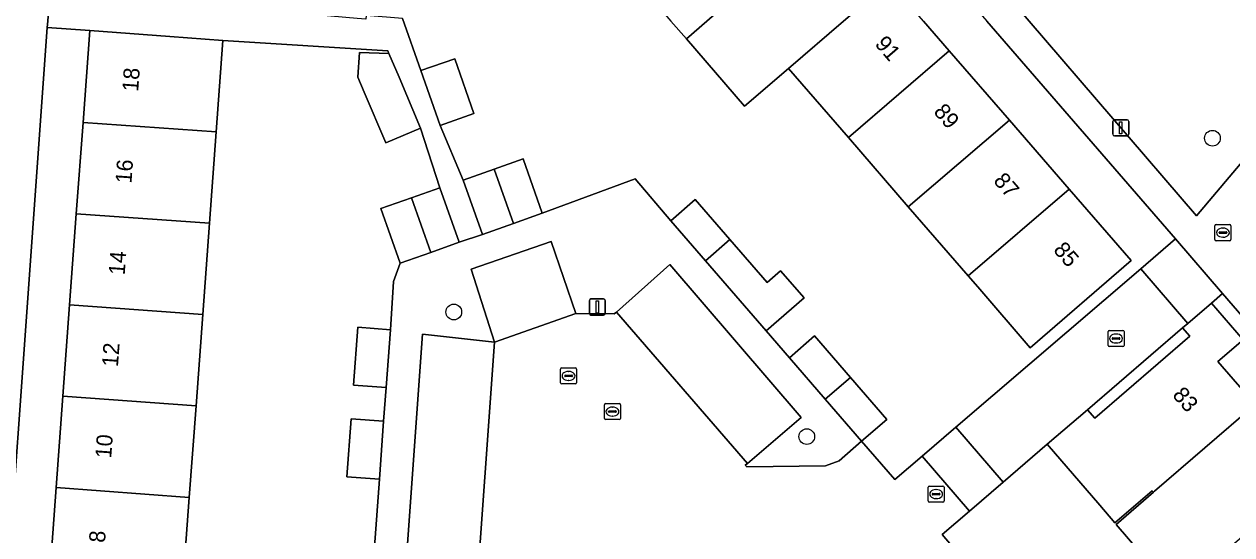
# Model space of a CAD drawing. Extents: x 160304 to 160955, y 383684 to 384161.
# Drawn here: x 160524.6 to 160599.7, y 383968 to 383999.8 of the extents above; entities that cross this region are included whole.
import ezdxf

# ---------------------------------------------------------------- set-up
doc = ezdxf.new("R2010")
doc.units = 0
for name, color, linetype in [('IMGEO_Boom', 7, 'Continuous'), ('IMGEO_Erf', 7, 'Continuous'), ('IMGEO_Groenvoorziening', 7, 'Continuous'), ('IMGEO_Kolk', 7, 'Continuous'), ('IMGEO_Lichtmast', 7, 'Continuous'), ('IMGEO_Muur', 7, 'Continuous'), ('IMGEO_Pand', 7, 'Continuous'), ('IMGEO_Pand_nummerreeks', 7, 'Continuous'), ('IMGEO_Parkeervlak_open', 7, 'Continuous'), ('IMGEO_Rijbaan_lokaal_open', 7, 'Continuous'), ('IMGEO_Rioolput', 7, 'Continuous'), ('IMGEO_Voetpad_open', 7, 'Continuous')]:
    doc.layers.add(name, color=color, linetype=linetype)

msp = doc.modelspace()

# ---------------------------------------------------------------- linework, layer by layer
at = {"layer": 'IMGEO_Boom'}
for centre in [(160598.466, 383992.708), (160551.283, 383981.891), (160573.236, 383974.138)]:
    msp.add_circle(centre, 0.489, dxfattribs=at)
at = {"layer": 'IMGEO_Erf'}
for points in [[(160527.389, 383982.34), (160527.806, 383988.006), (160528.225, 383993.695), (160528.645, 383999.401), (160525.998, 383999.592), (160522.302, 383948.238), (160524.866, 383948.053), (160525.298, 383953.917), (160525.715, 383959.593), (160526.134, 383965.285), (160526.553, 383970.972), (160526.971, 383976.651)], [(160599.096, 383983.036), (160598.414, 383982.45), (160600.377, 383980.168), (160598.806, 383978.817), (160601.124, 383976.14), (160604.854, 383971.83), (160608.58, 383967.526), (160612.311, 383963.216), (160616.036, 383958.913), (160619.776, 383954.593), (160623.509, 383950.28), (160627.234, 383945.977), (160630.965, 383941.666), (160634.791, 383937.247), (160631.011, 383933.975), (160628.454, 383931.789), (160638.073, 383937.196), (160637.034, 383939.15)], [(160590.695, 383975.813), (160591.158, 383975.278), (160597.055, 383980.383), (160596.609, 383980.898)]]:
    msp.add_lwpolyline(points, close=True, dxfattribs=at)
for points in [[(160548.095, 384000.159), (160549.241, 383996.917), (160551.35, 383997.651), (160552.539, 383994.235), (160550.43, 383993.501), (160551.866, 383990.106), (160553.798, 383990.791), (160555.59, 383991.426), (160556.789, 383988.043), (160562.568, 383990.188), (160564.778, 383987.564), (160566.305, 383988.886), (160568.461, 383986.396), (160570.765, 383983.734), (160571.603, 383984.46), (160573.066, 383982.77), (160570.701, 383980.722), (160572.156, 383979.048), (160573.716, 383980.399), (160575.946, 383977.823), (160578.206, 383975.212), (160576.646, 383973.861), (160578.717, 383971.472), (160580.412, 383972.926), (160582.507, 383974.723), (160594.005, 383984.587), (160596.174, 383986.448), (160584.428, 384000)], [(160580.501, 384000), (160582.098, 383998.155), (160585.838, 383993.835), (160589.554, 383989.543), (160593.406, 383985.093), (160587.14, 383979.669), (160583.867, 383983.449), (160583.274, 383984.134), (160579.547, 383988.439), (160575.822, 383992.743), (160572.091, 383997.052), (160569.367, 383994.694), (160565.747, 383998.888), (160564.787, 384000)], [(160546.35, 383967.283), (160546.654, 383971.48), (160544.641, 383971.628), (160544.906, 383975.237), (160546.919, 383975.089), (160547.072, 383977.191), (160545.043, 383977.341), (160545.308, 383980.938), (160547.337, 383980.788), (160547.526, 383983.799), (160547.95, 383984.927), (160546.745, 383988.324), (160548.66, 383989.003), (160550.415, 383989.625), (160549.217, 383993.34), (160547.055, 383992.422), (160545.715, 383995.579), (160545.322, 383996.504), (160545.416, 383998.032), (160547.25, 383997.975), (160547.178, 383998.146), (160536.928, 383998.791), (160536.509, 383993.101), (160536.09, 383987.411), (160535.672, 383981.732), (160535.254, 383976.043), (160534.835, 383970.354), (160534.417, 383964.675)], [(160596.19, 383964.361), (160592.479, 383968.676), (160594.792, 383970.673), (160594.721, 383970.755), (160592.405, 383968.763), (160591.453, 383969.87), (160588.193, 383973.661), (160585.448, 383971.301), (160583.355, 383969.502), (160581.663, 383968.047), (160584.668, 383964.501)]]:
    msp.add_lwpolyline(points, dxfattribs=at)
at = {"layer": 'IMGEO_Groenvoorziening'}
msp.add_lwpolyline([(160606.162, 383998.161), (160604.57, 384000), (160596.111, 384009.752), (160594.309, 384011.829), (160586.807, 384020.477), (160586.439, 384013.993), (160586.254, 384013.314), (160585.808, 384012.766), (160585.177, 384012.446), (160584.647, 384012.392), (160578.455, 384012.669), (160578.729, 384009.705), (160587.067, 384000), (160597.474, 383987.879), (160605.836, 383997.776)], close=True, dxfattribs=at)
at = {"layer": 'IMGEO_Kolk'}
for p, q in [((160592.047, 383980.743), (160592.899, 383980.743)), ((160591.972, 383979.817), (160591.972, 383980.669)), ((160592.231, 383980.237), (160592.231, 383980.249)), ((160592.669, 383980.2), (160592.271, 383980.2)), ((160592.274, 383980.286), (160592.672, 383980.286)), ((160592.483, 383979.963), (160592.458, 383979.963)), ((160592.46, 383980.523), (160592.485, 383980.523)), ((160592.715, 383980.249), (160592.715, 383980.237)), ((160592.973, 383980.669), (160592.973, 383979.817)), ((160592.899, 383979.743), (160592.047, 383979.743)), ((160560.724, 383976.192), (160561.576, 383976.192)), ((160560.649, 383975.266), (160560.649, 383976.118)), ((160560.908, 383975.686), (160560.908, 383975.698)), ((160561.346, 383975.649), (160560.948, 383975.649)), ((160560.951, 383975.735), (160561.349, 383975.735)), ((160561.137, 383975.972), (160561.162, 383975.972)), ((160561.392, 383975.698), (160561.392, 383975.686)), ((160561.65, 383976.118), (160561.65, 383975.266)), ((160561.576, 383975.192), (160560.724, 383975.192)), ((160561.16, 383975.412), (160561.135, 383975.412)), ((160580.78, 383970.133), (160580.78, 383970.985)), ((160580.855, 383971.059), (160581.707, 383971.059)), ((160581.781, 383970.985), (160581.781, 383970.133)), ((160581.039, 383970.553), (160581.039, 383970.565)), ((160581.477, 383970.516), (160581.079, 383970.516)), ((160581.082, 383970.602), (160581.48, 383970.602)), ((160581.291, 383970.279), (160581.266, 383970.279)), ((160581.268, 383970.839), (160581.293, 383970.839)), ((160581.523, 383970.565), (160581.523, 383970.553)), ((160581.707, 383970.059), (160580.855, 383970.059))]:
    msp.add_line(p, q, dxfattribs=at)
for points in [[(160592.047, 383980.743), (160592.899, 383980.743)], [(160591.972, 383979.817), (160591.972, 383980.669)], [(160592.973, 383980.669), (160592.973, 383979.817)], [(160592.899, 383979.743), (160592.047, 383979.743)], [(160560.724, 383976.192), (160561.576, 383976.192)], [(160560.649, 383975.266), (160560.649, 383976.118)], [(160561.65, 383976.118), (160561.65, 383975.266)], [(160561.576, 383975.192), (160560.724, 383975.192)], [(160580.78, 383970.133), (160580.78, 383970.985)], [(160580.855, 383971.059), (160581.707, 383971.059)], [(160581.781, 383970.985), (160581.781, 383970.133)], [(160581.707, 383970.059), (160580.855, 383970.059)]]:
    msp.add_lwpolyline(points, dxfattribs=at)
for centre, radius, start, end in [((160592.049, 383980.667), 0.0765, 91.55205, 178.44795), ((160592.049, 383980.667), 0.0765, 91.55205, 178.44795), ((160592.897, 383980.667), 0.0765, 1.55205, 88.44795), ((160592.897, 383980.667), 0.0765, 1.55205, 88.44795), ((160592.271, 383980.246), 0.0403, 85.87752, 175.75265), ((160592.268, 383980.236), 0.0366, 178.93798, 274.71019), ((160592.672, 383980.243), 0.043, 264.86636, 352.45326), ((160592.676, 383980.248), 0.0386, 1.73085, 96.63898), ((160592.049, 383979.819), 0.0765, 181.55205, 268.44795), ((160592.049, 383979.819), 0.0765, 181.55205, 268.44795), ((160592.897, 383979.819), 0.0765, 271.55205, 358.44795), ((160592.897, 383979.819), 0.0765, 271.55205, 358.44795), ((160560.726, 383976.116), 0.0765, 91.55205, 178.44795), ((160560.726, 383976.116), 0.0765, 91.55205, 178.44795), ((160561.574, 383976.116), 0.0765, 1.55205, 88.44795), ((160561.574, 383976.116), 0.0765, 1.55205, 88.44795), ((160560.948, 383975.695), 0.0403, 85.87752, 175.75265), ((160560.945, 383975.685), 0.0366, 178.93798, 274.71019), ((160561.349, 383975.692), 0.043, 264.86636, 352.45326), ((160561.353, 383975.697), 0.0386, 1.73085, 96.63898), ((160560.726, 383975.268), 0.0765, 181.55205, 268.44795), ((160560.726, 383975.268), 0.0765, 181.55205, 268.44795), ((160561.574, 383975.268), 0.0765, 271.55205, 358.44795), ((160561.574, 383975.268), 0.0765, 271.55205, 358.44795), ((160580.857, 383970.983), 0.0765, 91.55205, 178.44795), ((160580.857, 383970.983), 0.0765, 91.55205, 178.44795), ((160581.705, 383970.983), 0.0765, 1.55205, 88.44795), ((160581.705, 383970.983), 0.0765, 1.55205, 88.44795), ((160581.079, 383970.562), 0.0403, 85.87752, 175.75265), ((160581.076, 383970.552), 0.0366, 178.93798, 274.71019), ((160581.48, 383970.559), 0.043, 264.86636, 352.45326), ((160581.484, 383970.564), 0.0386, 1.73085, 96.63898), ((160580.857, 383970.135), 0.0765, 181.55205, 268.44795), ((160580.857, 383970.135), 0.0765, 181.55205, 268.44795), ((160581.705, 383970.135), 0.0765, 271.55205, 358.44795), ((160581.705, 383970.135), 0.0765, 271.55205, 358.44795)]:
    msp.add_arc(centre, radius, start, end, dxfattribs=at)
for centre, major_axis, ratio, start_param, end_param in [((160592.459, 383980.243), (-0.387, 0.002), 0.722429, 4.712389, 7.853982), ((160592.484, 383980.243), (-0.39, 0.002), 0.717154, 1.570796, 4.712389), ((160561.136, 383975.692), (-0.387, 0.002), 0.722429, 4.712389, 7.853982), ((160561.161, 383975.692), (-0.39, 0.002), 0.717154, 1.570796, 4.712389), ((160581.267, 383970.559), (-0.387, 0.002), 0.722429, 4.712389, 7.853982), ((160581.292, 383970.559), (-0.39, 0.002), 0.717154, 1.570796, 4.712389)]:
    msp.add_ellipse(centre, major_axis=major_axis, ratio=ratio, start_param=start_param, end_param=end_param, dxfattribs=at)
at = {"layer": 'IMGEO_Lichtmast'}
for p, q in [((160592.27, 383992.95), (160592.27, 383993.75)), ((160592.27, 383993.75), (160592.27, 383992.95)), ((160592.37, 383993.85), (160593.16, 383993.85)), ((160593.16, 383993.85), (160592.37, 383993.85)), ((160593.26, 383993.75), (160593.26, 383992.95)), ((160593.26, 383992.95), (160593.26, 383993.75)), ((160593.16, 383992.85), (160592.37, 383992.85)), ((160592.37, 383992.85), (160593.16, 383992.85)), ((160559.713, 383981.802), (160559.713, 383982.602)), ((160559.713, 383982.602), (160559.713, 383981.802)), ((160559.813, 383982.702), (160560.603, 383982.702)), ((160560.603, 383982.702), (160559.813, 383982.702)), ((160560.703, 383982.602), (160560.703, 383981.802)), ((160560.703, 383981.802), (160560.703, 383982.602)), ((160560.603, 383981.702), (160559.813, 383981.702)), ((160559.813, 383981.702), (160560.603, 383981.702))]:
    msp.add_line(p, q, dxfattribs=at)
for points in [[(160592.69, 383993.725), (160592.84, 383993.725), (160592.84, 383992.975), (160592.69, 383992.975), (160592.69, 383993.725)], [(160560.133, 383982.577), (160560.283, 383982.577), (160560.283, 383981.827), (160560.133, 383981.827), (160560.133, 383982.577)]]:
    msp.add_lwpolyline(points, dxfattribs=at)
for centre, start, end in [((160592.37, 383993.75), 90, 180), ((160592.37, 383993.75), 90, 180), ((160593.16, 383993.75), 0, 90), ((160593.16, 383993.75), 360, 90), ((160592.37, 383992.95), 180, 270), ((160592.37, 383992.95), 180, 270), ((160593.16, 383992.95), 270, 0), ((160593.16, 383992.95), 270, 0), ((160559.813, 383982.602), 90, 180), ((160559.813, 383982.602), 90, 180), ((160560.603, 383982.602), 0, 90), ((160560.603, 383982.602), 360, 90), ((160559.813, 383981.802), 180, 270), ((160559.813, 383981.802), 180, 270), ((160560.603, 383981.802), 270, 0), ((160560.603, 383981.802), 270, 0)]:
    msp.add_arc(centre, 0.1, start, end, dxfattribs=at)
at = {"layer": 'IMGEO_Muur'}
for points in [[(160556.789, 383988.043), (160562.568, 383990.188), (160564.778, 383987.564)], [(160585.448, 383971.301), (160588.193, 383973.661)], [(160583.355, 383969.502), (160585.448, 383971.301)], [(160581.663, 383968.047), (160583.355, 383969.502)]]:
    msp.add_lwpolyline(points, dxfattribs=at)
at = {"layer": 'IMGEO_Pand'}
for points in [[(160565.747, 383998.888), (160567.029, 384000), (160568.47, 384001.25), (160568.36, 384001.38), (160571.96, 384004.48), (160571.874, 384004.582), (160568.208, 384008.753), (160561.911, 384003.332), (160564.787, 384000)], [(160572.091, 383997.052), (160575.523, 384000), (160578.378, 384002.452), (160574.541, 384006.884), (160571.874, 384004.582), (160571.96, 384004.48), (160568.36, 384001.38), (160568.47, 384001.25), (160567.029, 384000), (160565.747, 383998.888), (160569.367, 383994.694)], [(160572.091, 383997.052), (160575.822, 383992.743), (160582.098, 383998.155), (160580.501, 384000), (160578.378, 384002.452), (160575.523, 384000)], [(160528.225, 383993.695), (160536.509, 383993.101), (160536.928, 383998.791), (160533.632, 383999.034), (160528.645, 383999.401)], [(160547.877, 383996.497), (160547.25, 383997.975), (160545.416, 383998.032), (160545.322, 383996.504), (160545.715, 383995.579), (160547.055, 383992.422), (160549.217, 383993.34)], [(160579.547, 383988.439), (160585.838, 383993.835), (160582.098, 383998.155), (160575.822, 383992.743)], [(160549.241, 383996.917), (160550.43, 383993.501), (160552.539, 383994.235), (160551.35, 383997.651)], [(160528.225, 383993.695), (160527.806, 383988.006), (160536.09, 383987.411), (160536.509, 383993.101)], [(160579.547, 383988.439), (160583.274, 383984.134), (160589.554, 383989.543), (160585.838, 383993.835)], [(160553.798, 383990.791), (160554.99, 383987.405), (160556.789, 383988.043), (160555.59, 383991.426)], [(160553.798, 383990.791), (160551.866, 383990.106), (160553.065, 383986.723), (160554.99, 383987.405)], [(160548.66, 383989.003), (160546.745, 383988.324), (160547.95, 383984.927), (160549.857, 383985.603)], [(160548.66, 383989.003), (160549.857, 383985.603), (160551.619, 383986.228), (160550.415, 383989.625)], [(160583.274, 383984.134), (160583.867, 383983.449), (160587.14, 383979.669), (160593.406, 383985.093), (160589.554, 383989.543)], [(160566.932, 383985.077), (160568.461, 383986.396), (160566.305, 383988.886), (160564.778, 383987.564)], [(160527.389, 383982.34), (160535.672, 383981.732), (160536.09, 383987.411), (160527.806, 383988.006)], [(160568.461, 383986.396), (160566.932, 383985.077), (160570.701, 383980.722), (160573.066, 383982.77), (160571.603, 383984.46), (160570.765, 383983.734)], [(160526.971, 383976.651), (160535.254, 383976.043), (160535.672, 383981.732), (160527.389, 383982.34)], [(160594.792, 383970.673), (160594.87, 383970.74), (160601.124, 383976.14), (160598.806, 383978.817), (160600.377, 383980.168), (160598.414, 383982.45), (160596.935, 383981.178), (160596.609, 383980.898), (160597.055, 383980.383), (160591.158, 383975.278), (160590.695, 383975.813), (160588.193, 383973.661), (160591.453, 383969.87), (160592.405, 383968.763), (160594.721, 383970.755)], [(160547.072, 383977.191), (160547.337, 383980.788), (160545.308, 383980.938), (160545.043, 383977.341)], [(160574.383, 383976.476), (160575.946, 383977.823), (160573.716, 383980.399), (160572.156, 383979.048)], [(160574.383, 383976.476), (160576.646, 383973.861), (160578.206, 383975.212), (160575.946, 383977.823)], [(160526.971, 383976.651), (160526.553, 383970.972), (160534.835, 383970.354), (160535.254, 383976.043)], [(160604.854, 383971.83), (160601.124, 383976.14), (160594.87, 383970.74), (160594.792, 383970.673), (160592.479, 383968.676), (160596.19, 383964.361), (160598.52, 383966.37)], [(160546.654, 383971.48), (160546.919, 383975.089), (160544.906, 383975.237), (160544.641, 383971.628)], [(160534.835, 383970.354), (160526.553, 383970.972), (160526.134, 383965.285), (160534.417, 383964.675)]]:
    msp.add_lwpolyline(points, close=True, dxfattribs=at)
at = {"layer": 'IMGEO_Parkeervlak_open'}
for points in [[(160558.87, 383981.795), (160557.333, 383986.279), (160552.354, 383984.557), (160553.811, 383980.008)], [(160561.409, 383981.875), (160569.541, 383972.466), (160572.888, 383975.325), (160564.721, 383984.839)], [(160552.611, 383963.202), (160553.811, 383980.008), (160549.341, 383980.51), (160548.132, 383963.691)]]:
    msp.add_lwpolyline(points, close=True, dxfattribs=at)
at = {"layer": 'IMGEO_Rijbaan_lokaal_open'}
for points in [[(160596.174, 383986.448), (160594.005, 383984.587), (160596.935, 383981.178), (160598.414, 383982.45), (160599.096, 383983.036)], [(160588.193, 383973.661), (160590.695, 383975.813), (160596.609, 383980.898), (160596.935, 383981.178), (160594.005, 383984.587), (160582.507, 383974.723), (160585.448, 383971.301)], [(160585.448, 383971.301), (160582.507, 383974.723), (160580.412, 383972.926), (160583.355, 383969.502)]]:
    msp.add_lwpolyline(points, close=True, dxfattribs=at)
msp.add_lwpolyline([(160584.668, 383964.501), (160581.663, 383968.047), (160583.355, 383969.502), (160580.412, 383972.926), (160578.717, 383971.472), (160576.646, 383973.861), (160575.255, 383972.626), (160574.403, 383972.324), (160569.515, 383972.251), (160569.413, 383972.353), (160569.541, 383972.466), (160561.409, 383981.875), (160561.257, 383981.774), (160558.87, 383981.795), (160553.811, 383980.008), (160552.611, 383963.202)], dxfattribs=at)
at = {"layer": 'IMGEO_Rioolput'}
for p, q in [((160598.617, 383986.404), (160598.617, 383987.256)), ((160598.692, 383987.33), (160599.544, 383987.33)), ((160598.876, 383986.824), (160598.876, 383986.836)), ((160599.314, 383986.787), (160598.916, 383986.787)), ((160598.919, 383986.873), (160599.317, 383986.873)), ((160599.105, 383987.11), (160599.13, 383987.11)), ((160599.36, 383986.836), (160599.36, 383986.824)), ((160599.618, 383987.256), (160599.618, 383986.404)), ((160599.544, 383986.33), (160598.692, 383986.33)), ((160599.128, 383986.55), (160599.103, 383986.55)), ((160557.92, 383977.488), (160557.92, 383978.34)), ((160557.995, 383978.414), (160558.847, 383978.414)), ((160558.179, 383977.908), (160558.179, 383977.92)), ((160558.617, 383977.871), (160558.219, 383977.871)), ((160558.222, 383977.957), (160558.62, 383977.957)), ((160558.408, 383978.194), (160558.433, 383978.194)), ((160558.663, 383977.92), (160558.663, 383977.908)), ((160558.921, 383978.34), (160558.921, 383977.488)), ((160558.847, 383977.414), (160557.995, 383977.414)), ((160558.431, 383977.634), (160558.406, 383977.634))]:
    msp.add_line(p, q, dxfattribs=at)
for points in [[(160598.617, 383986.404), (160598.617, 383987.256)], [(160598.692, 383987.33), (160599.544, 383987.33)], [(160599.618, 383987.256), (160599.618, 383986.404)], [(160599.544, 383986.33), (160598.692, 383986.33)], [(160557.92, 383977.488), (160557.92, 383978.34)], [(160557.995, 383978.414), (160558.847, 383978.414)], [(160558.921, 383978.34), (160558.921, 383977.488)], [(160558.847, 383977.414), (160557.995, 383977.414)]]:
    msp.add_lwpolyline(points, dxfattribs=at)
for centre, radius, start, end in [((160598.694, 383987.254), 0.0765, 91.55205, 178.44795), ((160598.694, 383987.254), 0.0765, 91.55205, 178.44795), ((160598.916, 383986.833), 0.0403, 85.87752, 175.75265), ((160598.913, 383986.823), 0.0366, 178.93798, 274.71019), ((160599.317, 383986.83), 0.043, 264.86636, 352.45326), ((160599.321, 383986.835), 0.0386, 1.73085, 96.63898), ((160599.542, 383987.254), 0.0765, 1.55205, 88.44795), ((160599.542, 383987.254), 0.0765, 1.55205, 88.44795), ((160598.694, 383986.406), 0.0765, 181.55205, 268.44795), ((160598.694, 383986.406), 0.0765, 181.55205, 268.44795), ((160599.542, 383986.406), 0.0765, 271.55205, 358.44795), ((160599.542, 383986.406), 0.0765, 271.55205, 358.44795), ((160557.997, 383978.338), 0.0765, 91.55205, 178.44795), ((160557.997, 383978.338), 0.0765, 91.55205, 178.44795), ((160558.219, 383977.917), 0.0403, 85.87752, 175.75265), ((160558.216, 383977.907), 0.0366, 178.93798, 274.71019), ((160558.62, 383977.914), 0.043, 264.86636, 352.45326), ((160558.624, 383977.919), 0.0386, 1.73085, 96.63898), ((160558.845, 383978.338), 0.0765, 1.55205, 88.44795), ((160558.845, 383978.338), 0.0765, 1.55205, 88.44795), ((160557.997, 383977.49), 0.0765, 181.55205, 268.44795), ((160557.997, 383977.49), 0.0765, 181.55205, 268.44795), ((160558.845, 383977.49), 0.0765, 271.55205, 358.44795), ((160558.845, 383977.49), 0.0765, 271.55205, 358.44795)]:
    msp.add_arc(centre, radius, start, end, dxfattribs=at)
for centre, major_axis, ratio, start_param, end_param in [((160599.104, 383986.83), (-0.387, 0.002), 0.722429, 4.712389, 7.853982), ((160599.129, 383986.83), (-0.39, 0.002), 0.717154, 1.570796, 4.712389), ((160558.407, 383977.914), (-0.387, 0.002), 0.722429, 4.712389, 7.853982), ((160558.432, 383977.914), (-0.39, 0.002), 0.717154, 1.570796, 4.712389)]:
    msp.add_ellipse(centre, major_axis=major_axis, ratio=ratio, start_param=start_param, end_param=end_param, dxfattribs=at)
at = {"layer": 'IMGEO_Voetpad_open'}
for points in [[(160518.776, 383947.168), (160518.729, 383946.518), (160519.227, 383946.483), (160518.953, 383942.703), (160518.455, 383942.738), (160517.105, 383924.059), (160518.927, 383923.923), (160519.059, 383925.551), (160519.677, 383933.96), (160519.798, 383935.598), (160519.906, 383937.041), (160520.34, 383942.858), (160520.599, 383946.385), (160522.16, 383946.27), (160522.302, 383948.238), (160525.998, 383999.592), (160526.027, 384000), (160526.157, 384001.805), (160526.404, 384005.17), (160524.792, 384005.245), (160525.428, 384014.213), (160526.037, 384022.511), (160526.375, 384026.574)], [(160617.179, 383966.719), (160616.269, 383967.769), (160601.248, 383985.099), (160609.035, 383994.079), (160605.836, 383997.776), (160597.474, 383987.879), (160587.067, 384000), (160578.729, 384009.705), (160578.455, 384012.669), (160576.669, 384014.76), (160575.499, 384016.128), (160572.574, 384019.551), (160572.716, 384022.448), (160567.161, 384022.807), (160576.438, 384011.974), (160576.873, 384008.716), (160584.428, 384000), (160596.174, 383986.448), (160599.096, 383983.036), (160637.034, 383939.15), (160638.073, 383937.196), (160638.701, 383936.015), (160653.56, 383908.079), (160657.72, 383910.303)], [(160548.132, 383963.691), (160549.341, 383980.51), (160553.811, 383980.008), (160552.354, 383984.557), (160557.333, 383986.279), (160558.87, 383981.795), (160561.257, 383981.774), (160561.409, 383981.875), (160564.721, 383984.839), (160572.888, 383975.325), (160569.541, 383972.466), (160569.413, 383972.353), (160569.515, 383972.251), (160574.403, 383972.324), (160575.255, 383972.626), (160576.646, 383973.861), (160574.383, 383976.476), (160572.156, 383979.048), (160570.701, 383980.722), (160566.932, 383985.077), (160564.778, 383987.564), (160562.568, 383990.188), (160556.789, 383988.043), (160554.99, 383987.405), (160553.065, 383986.723), (160551.619, 383986.228), (160549.857, 383985.603), (160547.95, 383984.927), (160547.526, 383983.799), (160547.337, 383980.788), (160547.072, 383977.191), (160546.919, 383975.089), (160546.654, 383971.48), (160546.35, 383967.283)]]:
    msp.add_lwpolyline(points, dxfattribs=at)
msp.add_lwpolyline([(160541.761, 384000.478), (160538.402, 384000.781), (160534.073, 384001.224), (160532.054, 384001.372), (160526.157, 384001.805), (160526.027, 384000), (160525.998, 383999.592), (160528.645, 383999.401), (160533.632, 383999.034), (160536.928, 383998.791), (160547.178, 383998.146), (160547.25, 383997.975), (160547.877, 383996.497), (160549.217, 383993.34), (160550.415, 383989.625), (160551.619, 383986.228), (160553.065, 383986.723), (160551.866, 383990.106), (160550.43, 383993.501), (160549.241, 383996.917), (160548.095, 384000.159), (160545.829, 384000.347), (160545.808, 384000.116), (160545.279, 384000.164)], close=True, dxfattribs=at)

# ---------------------------------------------------------------- texts
at = {"layer": 'IMGEO_Pand_nummerreeks'}
for s, rotation, p in [('91', 310.88331, (160577.423, 383998.545)), ('18', 85.79086, (160531.652, 383995.577)), ('89', 310.88331, (160581.074, 383994.327)), ('16', 85.79086, (160531.232, 383989.869)), ('87', 310.88331, (160584.798, 383990.025)), ('85', 310.88331, (160588.523, 383985.722)), ('14', 85.79086, (160530.812, 383984.164)), ('12', 85.79086, (160530.393, 383978.455)), ('83', 311.17991, (160595.929, 383976.689)), ('10', 85.79086, (160529.973, 383972.756)), ('8', 85.79086, (160529.587, 383967.51))]:
    msp.add_text(s, height=1, rotation=rotation, dxfattribs=at).set_placement(p)

doc.saveas('drawing.dxf')
